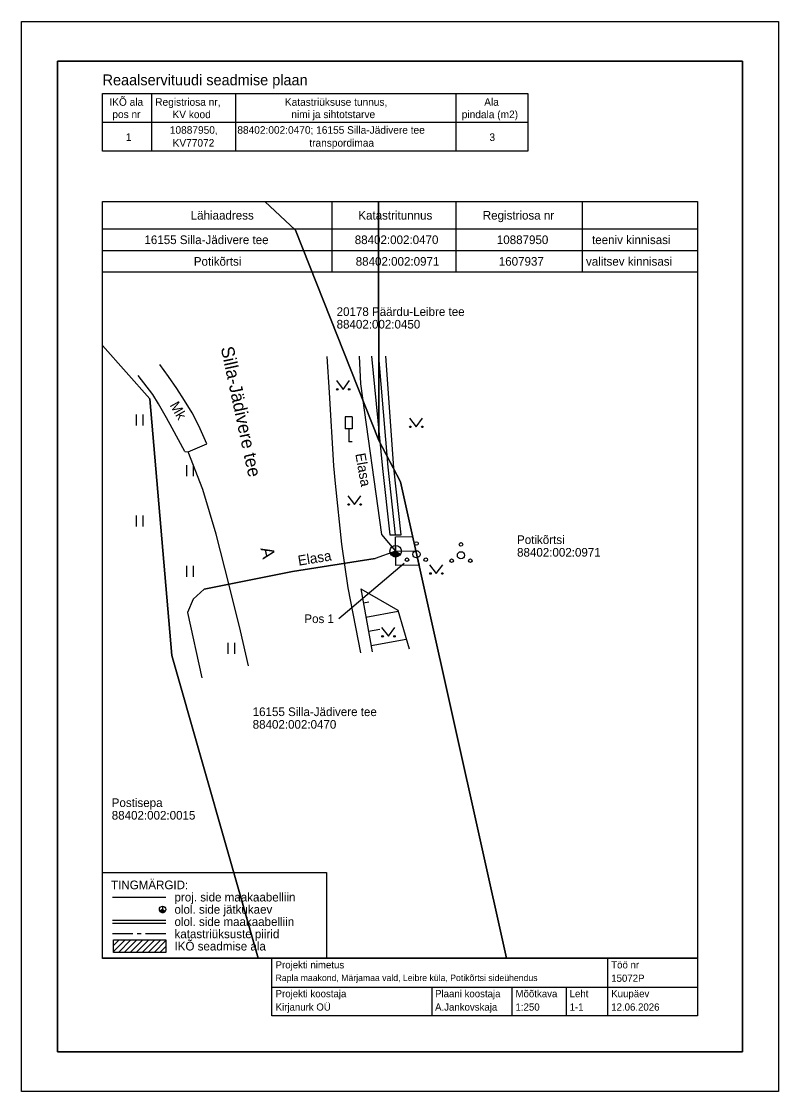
# Model space of a CAD drawing. Extents: x 523303.8 to 523356.3, y 6507511.5 to 6507585.7.
import ezdxf

# ---------------------------------------------------------------- set-up
doc = ezdxf.new("R2010")
doc.units = 0
for name, color, linetype in [('HALJASTUS', 7, 'Continuous'), ('KASUTUSALA', 7, 'Continuous'), ('LIIKLUS', 7, 'Continuous'), ('PIIR', 7, 'Continuous'), ('PR_SIDE', 7, 'Continuous'), ('PUU', 7, 'Continuous'), ('RELJEEF', 7, 'Continuous'), ('SIKAEV', 7, 'Continuous'), ('SITRASS', 7, 'Continuous'), ('TEE', 7, 'Continuous'), ('VORMISTUS', 7, 'Continuous')]:
    doc.layers.add(name, color=color, linetype=linetype)

msp = doc.modelspace()

# ---------------------------------------------------------------- linework, layer by layer
at = {"layer": 'HALJASTUS'}
for p, q in [((523325.671, 6507560.808), (523326.135, 6507560.202)), ((523326.135, 6507560.202), (523326.58, 6507560.808)), ((523311.792, 6507558.451), (523311.792, 6507557.689)), ((523312.248, 6507558.451), (523312.248, 6507557.689)), ((523330.744, 6507558.206), (523331.207, 6507557.599)), ((523331.207, 6507557.599), (523331.653, 6507558.206)), ((523315.292, 6507554.951), (523315.292, 6507554.189)), ((523315.748, 6507554.951), (523315.748, 6507554.189)), ((523326.469, 6507552.821), (523326.933, 6507552.214)), ((523326.933, 6507552.214), (523327.378, 6507552.821)), ((523311.792, 6507551.451), (523311.792, 6507550.689)), ((523312.248, 6507551.451), (523312.248, 6507550.689)), ((523315.292, 6507547.951), (523315.292, 6507547.189)), ((523315.748, 6507547.951), (523315.748, 6507547.189)), ((523332.134, 6507548.029), (523332.598, 6507547.422)), ((523332.598, 6507547.422), (523333.043, 6507548.029)), ((523328.813, 6507543.674), (523329.276, 6507543.067)), ((523329.276, 6507543.067), (523329.722, 6507543.674)), ((523318.154, 6507542.617), (523318.154, 6507541.856)), ((523318.609, 6507542.617), (523318.609, 6507541.856))]:
    msp.add_line(p, q, dxfattribs=at)
for points in [[(523328.113, 6507562.5), (523328.861, 6507554.717), (523329.376, 6507550.098), (523330.171, 6507550.108), (523329.647, 6507554.757), (523329.091, 6507562.507)], [(523329.774, 6507550.103), (523329.265, 6507554.807), (523328.618, 6507562.478)]]:
    msp.add_lwpolyline(points, dxfattribs=at)
for centre in [(523325.734, 6507560.202), (523326.562, 6507560.202), (523330.806, 6507557.599), (523331.635, 6507557.599), (523326.532, 6507552.214), (523327.361, 6507552.214), (523332.197, 6507547.422), (523333.025, 6507547.422), (523328.875, 6507543.067), (523329.704, 6507543.067)]:
    msp.add_circle(centre, 0.055, dxfattribs=at)
at = {"layer": 'KASUTUSALA'}
msp.add_lwpolyline([(523329.801, 6507547.978), (523329.765, 6507549.978), (523330.961, 6507549.999), (523331.405, 6507548.007)], close=True, dxfattribs=at)
at = {"layer": 'LIIKLUS'}
for p, q in [((523326.278, 6507558.304), (523326.278, 6507557.454)), ((523326.778, 6507558.304), (523326.278, 6507558.304)), ((523326.778, 6507558.304), (523326.778, 6507557.454)), ((523326.778, 6507557.454), (523326.278, 6507557.454)), ((523326.528, 6507557.454), (523326.528, 6507556.554)), ((523326.778, 6507556.554), (523326.528, 6507556.554))]:
    msp.add_line(p, q, dxfattribs=at)
at = {"layer": 'PIIR'}
for points in [[(523320.704, 6507573.229), (523322.84, 6507571.25), (523328.61, 6507556.65), (523328.601, 6507573.229)], [(523337.476, 6507520.729), (523330.12, 6507553.78), (523328.61, 6507556.65), (523322.84, 6507571.25), (523320.704, 6507573.229)], [(523328.601, 6507573.229), (523328.61, 6507556.65), (523330.12, 6507553.78), (523337.476, 6507520.729)], [(523320.243, 6507520.729), (523314.26, 6507541.73), (523312.75, 6507559.55), (523309.459, 6507563.232)], [(523309.459, 6507563.232), (523312.75, 6507559.55), (523314.26, 6507541.73), (523320.243, 6507520.729)]]:
    msp.add_lwpolyline(points, dxfattribs=at)
at = {"layer": 'PR_SIDE'}
msp.add_lwpolyline([(523329.783, 6507548.978), (523331.183, 6507549.004)], dxfattribs=at)
at = {"layer": 'PUU'}
for centre, radius in [((523331.223, 6507549.507), 0.125), ((523334.313, 6507549.439), 0.125), ((523330.573, 6507548.382), 0.125), ((523331.223, 6507548.757), 0.25), ((523331.873, 6507548.382), 0.125), ((523333.663, 6507548.314), 0.125), ((523334.313, 6507548.689), 0.25), ((523334.963, 6507548.314), 0.125)]:
    msp.add_circle(centre, radius, dxfattribs=at)
at = {"layer": 'RELJEEF'}
for p, q in [((523327.366, 6507546.37), (523328.165, 6507542.001)), ((523327.546, 6507545.387), (523327.931, 6507545.457)), ((523327.726, 6507544.403), (523329.958, 6507544.811)), ((523327.905, 6507543.419), (523328.682, 6507543.561)), ((523328.085, 6507542.435), (523330.515, 6507542.88))]:
    msp.add_line(p, q, dxfattribs=at)
msp.add_lwpolyline([(523327.366, 6507546.37), (523329.937, 6507544.884), (523330.713, 6507542.193)], dxfattribs=at)
at = {"layer": 'SIKAEV'}
for p, q in [((523329.783, 6507549.378), (523329.783, 6507548.978)), ((523329.783, 6507548.978), (523329.451, 6507548.758)), ((523329.783, 6507548.978), (523330.115, 6507548.758))]:
    msp.add_line(p, q, dxfattribs=at)
msp.add_circle((523329.783, 6507548.978), 0.4, dxfattribs=at)
for radius in [0.38, 0.36, 0.34, 0.32, 0.3, 0.28, 0.26, 0.24, 0.22, 0.2, 0.18, 0.16, 0.14, 0.12, 0.1, 0.08, 0.06, 0.04]:
    msp.add_arc((523329.783, 6507548.978), radius, 213.53047, 326.46953, dxfattribs=at)
at = {"layer": 'SITRASS'}
for points in [[(523327.251, 6507562.493), (523327.348, 6507560.59), (523328.802, 6507550.142)], [(523327.251, 6507562.493), (523327.348, 6507560.59), (523328.802, 6507550.142), (523329.783, 6507548.978)], [(523329.783, 6507548.978), (523328.364, 6507548.475), (523322.623, 6507547.566), (523316.509, 6507546.338), (523315.739, 6507545.634), (523315.354, 6507544.711), (523316.335, 6507540.195)], [(523316.509, 6507546.338), (523322.623, 6507547.566), (523328.364, 6507548.475)]]:
    msp.add_lwpolyline(points, dxfattribs=at)
at = {"layer": 'TEE'}
msp.add_line((523315.158, 6507555.885), (523315.404, 6507555.865), dxfattribs=at)
for points in [[(523316.693, 6507556.425), (523316.129, 6507557.662), (523315.67, 6507558.562), (523315.147, 6507559.429), (523314.608, 6507560.264), (523314.025, 6507561.098), (523313.423, 6507561.918)], [(523325.008, 6507562.475), (523325.17, 6507559.976), (523325.465, 6507554.896), (523325.585, 6507553.68), (523326.036, 6507549.464), (523326.461, 6507546.438), (523327.35, 6507541.917)], [(523315.158, 6507555.885), (523314.296, 6507557.504), (523313.895, 6507558.227), (523313.336, 6507559.189), (523312.944, 6507559.837), (523311.936, 6507561.173)], [(523319.588, 6507541.018), (523319.032, 6507543.441), (523318.24, 6507546.62), (523317.34, 6507550.144), (523316.419, 6507553.261), (523315.404, 6507555.865), (523316.693, 6507556.425)]]:
    msp.add_lwpolyline(points, dxfattribs=at)
at = {"layer": 'VORMISTUS'}
for p, q in [((523312.846, 6507580.734), (523312.846, 6507576.734)), ((523318.671, 6507580.734), (523318.671, 6507576.734)), ((523333.946, 6507580.734), (523333.946, 6507576.734)), ((523309.446, 6507578.734), (523338.946, 6507578.734)), ((523325.362, 6507573.229), (523325.362, 6507568.329)), ((523333.952, 6507573.229), (523333.952, 6507568.329)), ((523342.709, 6507573.229), (523342.709, 6507568.329)), ((523309.459, 6507571.329), (523350.709, 6507571.329)), ((523309.459, 6507569.829), (523350.709, 6507569.829)), ((523330.374, 6507548.127), (523325.854, 6507544.285)), ((523310.156, 6507524.97), (523313.85, 6507524.97)), ((523313.625, 6507524.12), (523313.438, 6507523.996)), ((523313.625, 6507524.345), (523313.625, 6507524.12)), ((523313.625, 6507524.12), (523313.812, 6507523.996)), ((523310.156, 6507523.381), (523313.85, 6507523.381)), ((523310.156, 6507523.159), (523313.85, 6507523.159)), ((523311.566, 6507522.42), (523310.155, 6507522.42)), ((523311.019, 6507522.007), (523310.209, 6507521.197)), ((523310.607, 6507522.007), (523310.209, 6507521.609)), ((523311.431, 6507522.007), (523310.557, 6507521.133)), ((523311.843, 6507522.007), (523310.969, 6507521.133)), ((523312.255, 6507522.007), (523311.381, 6507521.133)), ((523312.666, 6507522.007), (523311.793, 6507521.133)), ((523312.148, 6507522.42), (523311.857, 6507522.42)), ((523313.078, 6507522.007), (523312.205, 6507521.133)), ((523313.85, 6507522.42), (523312.439, 6507522.42)), ((523313.49, 6507522.007), (523312.616, 6507521.133)), ((523313.85, 6507521.955), (523313.028, 6507521.133)), ((523313.85, 6507521.543), (523313.44, 6507521.133)), ((523344.482, 6507520.729), (523344.482, 6507518.729)), ((523321.209, 6507518.729), (523350.709, 6507518.729)), ((523332.303, 6507518.729), (523332.303, 6507516.729)), ((523337.846, 6507518.729), (523337.846, 6507516.729)), ((523341.598, 6507518.729), (523341.598, 6507516.729)), ((523344.482, 6507518.729), (523344.482, 6507516.729))]:
    msp.add_line(p, q, dxfattribs=at)
for points in [[(523303.834, 6507585.729), (523356.334, 6507585.729), (523356.334, 6507511.479), (523303.834, 6507511.479)], [(523306.334, 6507514.229), (523353.834, 6507514.229), (523353.834, 6507582.979), (523306.334, 6507582.979)], [(523306.334, 6507582.979), (523353.834, 6507582.979), (523353.834, 6507514.229), (523306.334, 6507514.229)], [(523309.446, 6507580.734), (523338.946, 6507580.734), (523338.946, 6507576.734), (523309.446, 6507576.734)], [(523350.709, 6507520.729), (523309.459, 6507520.729), (523309.459, 6507573.229), (523350.709, 6507573.229)], [(523309.459, 6507573.229), (523350.709, 6507573.229), (523350.709, 6507568.329), (523309.459, 6507568.329)], [(523309.45, 6507520.72), (523309.45, 6507526.67), (523324.98, 6507526.67), (523324.98, 6507520.72)], [(523310.209, 6507522.007), (523313.85, 6507522.007), (523313.85, 6507521.133), (523310.209, 6507521.133)], [(523321.209, 6507520.729), (523350.709, 6507520.729), (523350.709, 6507516.729), (523321.209, 6507516.729)]]:
    msp.add_lwpolyline(points, close=True, dxfattribs=at)
msp.add_circle((523313.625, 6507524.12), 0.225, dxfattribs=at)
for radius in [0.214, 0.203, 0.191, 0.18, 0.169, 0.158, 0.146, 0.135, 0.124, 0.113, 0.101, 0.0901, 0.0788, 0.0676, 0.0563, 0.0451, 0.0338, 0.0225]:
    msp.add_arc((523313.625, 6507524.12), radius, 213.53047, 326.46953, dxfattribs=at)

# ---------------------------------------------------------------- texts
at = {"layer": 'PIIR'}
for s, p in [('20178 Päärdu-Leibre tee', (523325.689, 6507565.294)), ('88402:002:0450', (523325.689, 6507564.419)), ('Potikõrtsi', (523338.201, 6507549.47)), ('88402:002:0971', (523338.201, 6507548.595)), ('16155 Silla-Jädivere tee', (523319.869, 6507537.532)), ('88402:002:0470', (523319.869, 6507536.657)), ('Postisepa', (523310.097, 6507531.225)), ('88402:002:0015', (523310.097, 6507530.35))]:
    msp.add_text(s, height=0.6, dxfattribs=at).set_placement(p)
at = {"layer": 'SITRASS'}
for rotation, p in [(279.90664, (523326.985, 6507555.717)), (9.29014, (523323.064, 6507547.963))]:
    msp.add_text('Elasa', height=0.7, rotation=rotation, dxfattribs=at).set_placement(p)
at = {"layer": 'TEE'}
for s, height, rotation, p in [('Silla-Jädivere tee', 0.9, 282.16235, (523317.65, 6507563.077)), ('Mk', 0.7, 299.7118, (523314.099, 6507559.108)), ('A', 0.9, 282.16235, (523320.407, 6507549.166))]:
    msp.add_text(s, height=height, rotation=rotation, dxfattribs=at).set_placement(p)
at = {"layer": 'VORMISTUS'}
for s, height, p in [('Reaalservituudi seadmise plaan', 0.75, (523309.462, 6507581.296)), ('IKÕ ala', 0.525, (523309.935, 6507579.875)), ('Registriosa nr,', 0.525, (523313.114, 6507579.875)), ('Katastriüksuse tunnus,', 0.525, (523322.104, 6507579.875)), ('Ala', 0.525, (523335.925, 6507579.875)), ('pos nr', 0.525, (523310.14, 6507579.023)), ('KV kood', 0.525, (523314.311, 6507579.016)), ('nimi ja sihtotstarve', 0.525, (523322.549, 6507579.02)), ('pindala (m2)', 0.525, (523334.369, 6507579.016)), ('10887950,', 0.525, (523314.126, 6507577.934)), ('88402:002:0470; 16155 Silla-Jädivere tee', 0.525, (523318.807, 6507577.934)), ('1', 0.525, (523311.071, 6507577.434)), ('KV77072', 0.525, (523314.32, 6507577.04)), ('transpordimaa', 0.525, (523323.799, 6507577.04)), ('3', 0.525, (523336.285, 6507577.434)), ('Lähiaadress', 0.6, (523315.572, 6507571.979)), ('Katastritunnus', 0.6, (523327.194, 6507571.979)), ('Registriosa nr', 0.6, (523335.824, 6507571.979)), ('16155 Silla-Jädivere tee', 0.6, (523312.364, 6507570.279)), ('88402:002:0470', 0.6, (523326.947, 6507570.279)), ('10887950', 0.6, (523336.799, 6507570.279)), ('teeniv kinnisasi', 0.6, (523343.4, 6507570.279)), ('Potikõrtsi', 0.6, (523315.788, 6507568.779)), ('88402:002:0971', 0.6, (523327.014, 6507568.779)), ('1607937', 0.6, (523336.934, 6507568.779)), ('valitsev kinnisasi', 0.6, (523342.98, 6507568.779)), ('Pos 1', 0.6, (523323.454, 6507543.985)), ('TINGMÄRGID:', 0.6, (523310.05, 6507525.52)), ('proj. side maakaabelliin', 0.6, (523314.45, 6507524.67)), ('olol. side jätkukaev', 0.6, (523314.45, 6507523.82)), ('olol. side maakaabelliin', 0.6, (523314.45, 6507522.97)), ('katastriüksuste piirid', 0.6, (523314.45, 6507522.12)), ('IKÕ seadmise ala', 0.6, (523314.45, 6507521.27)), ('Projekti nimetus', 0.5, (523321.459, 6507520.025)), ('Töö nr', 0.5, (523344.731, 6507520.025)), ('Rapla maakond, Märjamaa vald, Leibre küla, Potikõrtsi sideühendus', 0.45, (523321.459, 6507519.147)), ('15072P', 0.5, (523344.731, 6507519.097)), ('Projekti koostaja', 0.5, (523321.459, 6507518.025)), ('Plaani koostaja', 0.5, (523332.516, 6507518.025)), ('Mõõtkava', 0.5, (523338.095, 6507518.025)), ('Leht', 0.5, (523341.847, 6507518.025)), ('Kuupäev', 0.5, (523344.731, 6507518.025)), ('Kirjanurk OÜ', 0.5, (523321.459, 6507517.097)), ('A.Jankovskaja', 0.5, (523332.516, 6507517.097)), ('1:250', 0.5, (523338.095, 6507517.097)), ('1-1', 0.5, (523341.847, 6507517.097)), ('12.06.2026', 0.5, (523344.731, 6507517.097))]:
    msp.add_text(s, height=height, dxfattribs=at).set_placement(p)

doc.saveas('drawing.dxf')
